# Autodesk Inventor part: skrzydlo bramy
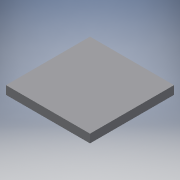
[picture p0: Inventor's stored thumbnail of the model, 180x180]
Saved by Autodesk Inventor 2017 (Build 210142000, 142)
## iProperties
Created: 2020-09
Part Number: skrzydlo bramy
Material: Generic
Document SubType Name: Modeling
Designer: X
Density: 1 g/cm^3
Appearance: Default
Author: X
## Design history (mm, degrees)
sketch "Szkic1"
  geometry: L1 (0, 0)-(1140, 0); L2 (1140, 0)-(1140, 1940); L3 (1140, 1940)-(0, 1940); L4 (0, 1940)-(0, 0); L5 (0, 1450)-(1140, 1450); L6 (0, 970)-(1140, 970); L7 (0, 480)-(1140, 480); L8 (1140, 0)-(1180, 0); L9 (1180, 0)-(1180, -40); L10 (1180, -40)-(1140, -40); L11 (1140, -40)-(1140, 0); L12 (1140, 1940)-(1180, 1940); L13 (1180, 1940)-(1180, 1980); L14 (1180, 1980)-(1140, 1980); L15 (1140, 1980)-(1140, 1940)
  constraints: 30 end point, 6 parallel, 5 perpendicular, 5 point on line, 3 horizontal, 2 midpoint
  dimensions: "d0" = 1140 distance of L2.end L3.end; "d1" = 1940 distance of L1.start L3.end; "d8" = 480 distance of L6.end L5.end
extrude "Wyciągnięcie proste1" new body sketch "Szkic1" distance "d9" = 4; taper "d10" = 0 deg
node "Bryła1"
